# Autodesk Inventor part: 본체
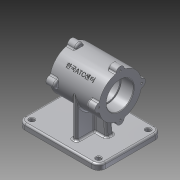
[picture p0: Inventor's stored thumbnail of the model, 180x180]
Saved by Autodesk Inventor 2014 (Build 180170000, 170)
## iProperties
Created: 2015-12
Part Number: 본체
Material: 알루미늄 6061
Document SubType Name: Modeling
Designer: basic
Density: 2.71 g/cm^3
Appearance: 알루미늄 - 평지
Mass: 1166.01 g
Surface Area: 816.021 cm^2
Volume: 430.263 cm^3
Author: basic
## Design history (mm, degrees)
sketch "스케치4"
  geometry: C1 r 37 at (0, 0); 1 further point
  constraints: 1 centre point, 1 coincident
  dimensions: "d14" = 74 diameter of C1
extrude "돌출3" new body sketch "스케치4" stored distance "d15" = 85; taper "d16" = 0 deg
sketch "스케치5"
  geometry: C1 r 7 at (0, 37); 2 further points
  constraints: 3 vertical alignment, 1 centre point, 2 other
  dimensions: "d17" = 14 diameter of C1
extrude "돌출4" join sketch "스케치5" distance "d18" = 15; taper "d19" = 0 deg
hole "구멍1" diameter "d22" = 3.242; stored, may be unused: countersink angle "d26" = 90 deg, drill point angle "d28" = 118 deg; dims "d20" = 10, "d21" = 10, "d23" = 9, "d24" = 4, "d25" = 2, "d27" = 11
node "작업 평면1"
sketch "스케치6"
  geometry: L1 (-55, 60)-(55, 60); L2 (55, 60)-(55, -80); L3 (55, -80)-(-55, -80); L4 (-55, -80)-(-55, 60); 2 further points
  constraints: 8 end point, 2 parallel, 1 horizontal, 1 midpoint, 1 perpendicular, 1 vertical alignment
  dimensions: "d33" = 110 distance of L1.start L1.end; "d34" = 140 distance of L3.end L1.start; "d35" = 80 distance from line of point (0, 0) L3
extrude "돌출5" join sketch "스케치6" distance "d36" = 10; taper "d37" = 0 deg
fillet "모깎기2" dims "d38" = 12
sketch "스케치7"
  geometry: L1 (-43, -80)-(43, -80) reference; L2 (-37, -4)-(37, -4); L3 (37, -4)-(37, 4); L4 (37, 4)-(-37, 4); L5 (-37, 4)-(-37, -4); 3 further points
  constraints: 8 end point, 2 midpoint, 2 parallel, 1 horizontal, 1 perpendicular, 1 vertical alignment
  dimensions: "d39" = 8 distance of L4.end L2.start; "d40" = 80 distance from line of L1 point (-37, 0); "d41" = 74 distance of L2.start L2.end
extrude "돌출6" join sketch "스케치7" stored distance "d42" = 10; taper "d43" = 0 deg
sketch "스케치8"
  geometry: L1 (-25, -70)-(-16.405, 0); L2 (25, -70)-(16.405, 0); L3 (48, -70)-(-68, -70) reference; L4 (-16.405, 0)-(16.405, 0); L5 (-25, -70)-(25, -70); 2 further points
  constraints: 8 end point, 2 midpoint, 1 coincident, 1 collinear, 1 horizontal, 1 parallel
  dimensions: "d44" = 97 deg angle of L3 L1; "d45" = 97 deg angle of L3 L2; "d46" = 50 distance of L2.start L1.start
extrude "돌출7" join sketch "스케치8" stored distance "d47" = 12; taper "d48" = 0 deg
fillet "모깎기3" dims "d49" = 3
fillet "모깎기4" dims "d50" = 3
hole "구멍2" diameter "d53" = 8; stored, may be unused: countersink angle "d57" = 90 deg, drill point angle "d59" = 118 deg; dims "d51" = 10, "d52" = 10, "d54" = 8, "d55" = 4, "d56" = 2, "d58" = 11
hole "구멍3" diameter "d62" = 8; stored, may be unused: countersink angle "d66" = 90 deg, drill point angle "d68" = 118 deg; dims "d60" = 10, "d61" = 10, "d63" = 8, "d64" = 4, "d65" = 2, "d67" = 11
hole "구멍4" diameter "d71" = 8; stored, may be unused: countersink angle "d75" = 90 deg, drill point angle "d77" = 118 deg; dims "d69" = 10, "d70" = 10, "d72" = 8, "d73" = 4, "d74" = 2, "d76" = 11
hole "구멍5" diameter "d80" = 8; stored, may be unused: countersink angle "d84" = 90 deg, drill point angle "d86" = 118 deg; dims "d78" = 10, "d79" = 10, "d81" = 8, "d82" = 4, "d83" = 2, "d85" = 11
fillet "모깎기5" dims "d87" = 3
chamfer "모따기1" distance "d88" = 1; stored, may be unused: second distance "d89" = 2, angle "d90" = 45 deg
fillet "모깎기6" dims "d91" = 3
hole "구멍6" diameter "d97" = 42; stored, may be unused: countersink angle "d101" = 90 deg, drill point angle "d103" = 118 deg; dims "d95" = 10, "d96" = 10, "d98" = 8, "d99" = 47, "d100" = 22, "d102" = 11
hole "구멍7" diameter "d106" = 47; stored, may be unused: countersink angle "d110" = 90 deg, drill point angle "d112" = 0 deg; dims "d107" = 8, "d108" = 47, "d109" = 22, "d111" = 22, "d126" = 10, "d127" = 10
chamfer "모따기2" distance "d113" = 1; stored, may be unused: second distance "d114" = 2, angle "d115" = 45 deg
fillet "모깎기7" dims "d116" = 0.3
node "작업 평면5"
  node "작업 평면4"
sketch "스케치10"
  geometry: 2 further points
  constraints: 1 coincident, 1 other
feature "엠보싱2" sketch "스케치10" dims "d32" = -80, "d124" = 0.5, "d125" = 0
node "솔리드2"
pattern_circular "원형 패턴1" dims angle "d30" = 360 deg
mirror "대칭1"
pattern_circular "원형 패턴2" dims angle "d93" = 360 deg
mirror "대칭2"
node "작업축2"
other parameters: "d122" = 45 deg, "d123" = 74
